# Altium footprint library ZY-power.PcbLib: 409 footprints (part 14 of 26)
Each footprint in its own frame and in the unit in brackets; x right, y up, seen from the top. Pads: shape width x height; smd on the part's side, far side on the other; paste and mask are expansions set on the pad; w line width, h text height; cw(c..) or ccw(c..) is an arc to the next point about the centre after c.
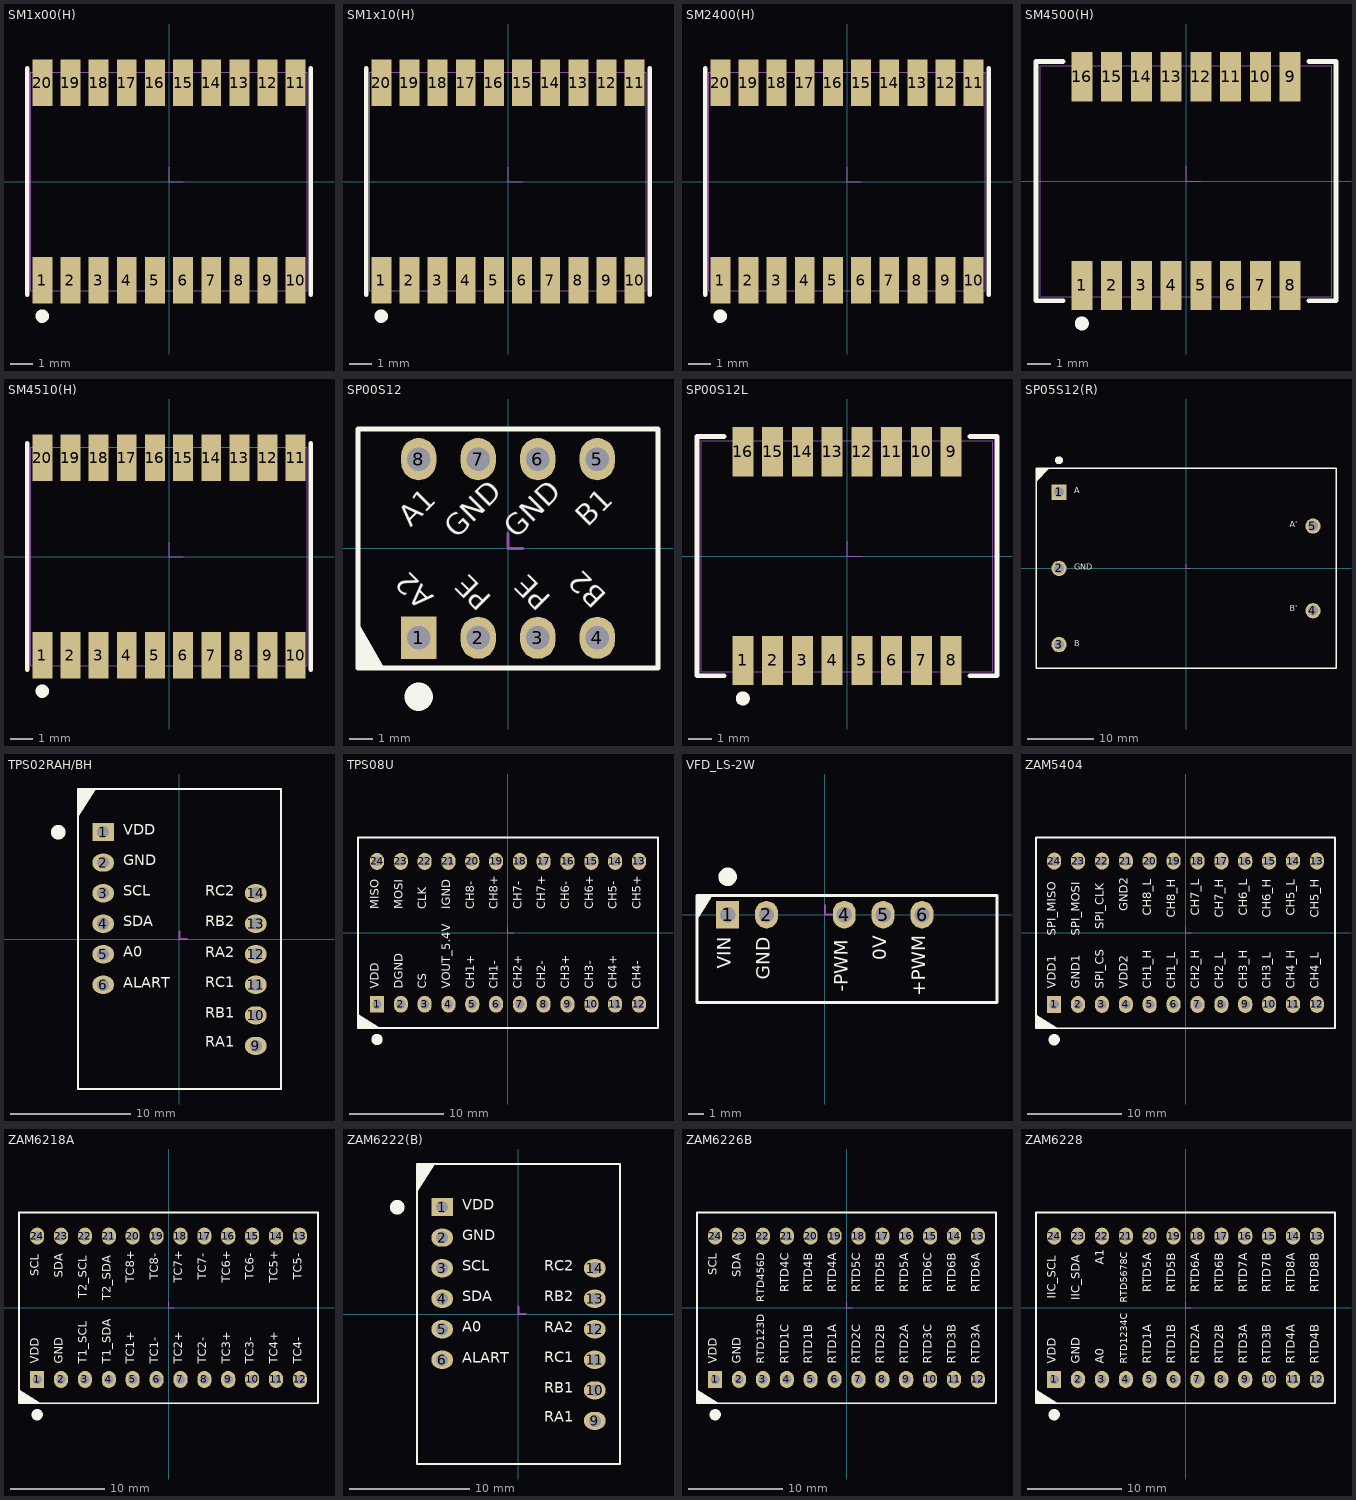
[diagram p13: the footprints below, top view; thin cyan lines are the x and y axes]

## SM1x00(H) [mm]
height 3
pads (20):
  rect 0.9x2.1 smd: 1(-5.715,-4.45) 2(-4.445,-4.45) 3(-3.175,-4.45) 4(-1.905,-4.45) 5(-0.635,-4.45) 6(0.635,-4.45) 7(1.905,-4.45) 8(3.175,-4.45) 9(4.445,-4.45) 10(5.715,-4.45) 11(5.715,4.45) 12(4.445,4.45) 13(3.175,4.45) 14(1.905,4.45) 15(0.635,4.45) 16(-0.635,4.45) 17(-1.905,4.45) 18(-3.175,4.45) 19(-4.445,4.45) 20(-5.715,4.45)
Top Overlay:
  circle w0.4: c-5.715,-6.074 r0.1
  lines w0.2: -6.4,-5.1 -6.4,5.1 ; 6.4,-5.1 6.4,5.1
Mechanical 13:
  lines w0.05: -6.225,-4.925 -6.225,4.925 6.225,4.925 6.225,-4.925 -6.225,-4.925
Mechanical 15:
  lines w0.05: 0,0.635 0,0 0.635,0

## SM1x10(H) [mm]
height 3
pads (20):
  rect 0.9x2.1 smd: 1(-5.715,-4.45) 2(-4.445,-4.45) 3(-3.175,-4.45) 4(-1.905,-4.45) 5(-0.635,-4.45) 6(0.635,-4.45) 7(1.905,-4.45) 8(3.175,-4.45) 9(4.445,-4.45) 10(5.715,-4.45) 11(5.715,4.45) 12(4.445,4.45) 13(3.175,4.45) 14(1.905,4.45) 15(0.635,4.45) 16(-0.635,4.45) 17(-1.905,4.45) 18(-3.175,4.45) 19(-4.445,4.45) 20(-5.715,4.45)
Top Overlay:
  circle w0.4: c-5.715,-6.074 r0.1
  lines w0.2: -6.4,-5.1 -6.4,5.1 ; 6.4,-5.1 6.4,5.1
Mechanical 13:
  lines w0.05: -6.225,-4.925 -6.225,4.925 6.225,4.925 6.225,-4.925 -6.225,-4.925
Mechanical 15:
  lines w0.05: 0,0.635 0,0 0.635,0

## SM2400(H) [mm]
height 3
pads (20):
  rect 0.9x2.1 smd: 1(-5.715,-4.45) 2(-4.445,-4.45) 3(-3.175,-4.45) 4(-1.905,-4.45) 5(-0.635,-4.45) 6(0.635,-4.45) 7(1.905,-4.45) 8(3.175,-4.45) 9(4.445,-4.45) 10(5.715,-4.45) 11(5.715,4.45) 12(4.445,4.45) 13(3.175,4.45) 14(1.905,4.45) 15(0.635,4.45) 16(-0.635,4.45) 17(-1.905,4.45) 18(-3.175,4.45) 19(-4.445,4.45) 20(-5.715,4.45)
Top Overlay:
  circle w0.4: c-5.715,-6.074 r0.1
  lines w0.2: -6.4,-5.1 -6.4,5.1 ; 6.4,-5.1 6.4,5.1
Mechanical 13:
  lines w0.05: -6.225,-4.925 6.225,-4.925 6.225,4.925 -6.225,4.925 -6.225,-4.925
Mechanical 15:
  lines w0.05: 0,0.635 0,0 0.635,0

## SM4500(H) [mm]
height 3
pads (16):
  rect 0.9x2.1 smd: 1(-4.445,-4.45) 2(-3.175,-4.45) 3(-1.905,-4.45) 4(-0.635,-4.45) 5(0.635,-4.45) 6(1.905,-4.45) 7(3.175,-4.45) 8(4.445,-4.45) 9(4.445,4.45) 10(3.175,4.45) 11(1.905,4.45) 12(0.635,4.45) 13(-0.635,4.45) 14(-1.905,4.45) 15(-3.175,4.45) 16(-4.445,4.45)
Top Overlay:
  circle w0.4: c-4.445,-6.074 r0.1
  lines w0.2: -5.232,-5.1 -6.4,-5.1 -6.4,5.1 -5.232,5.1 ; 5.232,-5.1 6.4,-5.1 6.4,5.1 5.232,5.1
Mechanical 13:
  lines w0.05: -6.225,-4.925 6.225,-4.925 6.225,4.925 -6.225,4.925 -6.225,-4.925
Mechanical 15:
  lines w0.05: 0,0.635 0,0 0.635,0
3D body "SM4500.stp": height 3.01, standoff -0.01, extent -6.225,-4.925 6.225,4.925

## SM4510(H) [mm]
height 3
pads (20):
  rect 0.9x2.1 smd: 1(-5.715,-4.45) 2(-4.445,-4.45) 3(-3.175,-4.45) 4(-1.905,-4.45) 5(-0.635,-4.45) 6(0.635,-4.45) 7(1.905,-4.45) 8(3.175,-4.45) 9(4.445,-4.45) 10(5.715,-4.45) 11(5.715,4.45) 12(4.445,4.45) 13(3.175,4.45) 14(1.905,4.45) 15(0.635,4.45) 16(-0.635,4.45) 17(-1.905,4.45) 18(-3.175,4.45) 19(-4.445,4.45) 20(-5.715,4.45)
Top Overlay:
  circle w0.4: c-5.715,-6.074 r0.1
  lines w0.2: -6.4,-5.1 -6.4,5.1 ; 6.4,-5.1 6.4,5.1
Mechanical 13:
  lines w0.05: -6.225,-4.925 -6.225,4.925 6.225,4.925 6.225,-4.925 -6.225,-4.925
Mechanical 15:
  lines w0.05: 0,0.635 0,0 0.635,0

## SP00S12 [mm]
height 7.7
pads (8):
  rect 1.5x1.8 hole 1: 1(-3.81,-3.81)
  oval 1.5x1.8 hole 1: 2(-1.27,-3.81) 3(1.27,-3.81) 4(3.81,-3.81) 5(3.81,3.81) 6(1.27,3.81) 7(-1.27,3.81) 8(-3.81,3.81)
Top Overlay:
  circle w1: c-3.81,-6.325 r0.1
  region: -5.284,-5.1 -6.4,-3.161 -6.4,-5.1
  lines w0.2: -6.4,-5.1 6.4,-5.1 6.4,5.1 -6.4,5.1 -6.4,-5.1
  text "A2" at -2.921,-1.849 h1.52
  text "PE" at -0.432,-1.88 h1.52
  text "PE" at 2.108,-1.88 h1.52
  text "B2" at 4.47,-1.778 h1.52
  text "A1" at -3.937,0.674 h1.52
  text "GND" at -1.981,0.178 h1.52
  text "GND" at 0.559,0.178 h1.52
  text "B1" at 3.607,0.674 h1.52
Mechanical 15:
  lines w0.127: 0,0.635 0,0 0.635,0
3D body: height 7.7, standoff 0, extent -6.4,-5.1 6.4,5.1
3D body "zhen01.stp": height 6.09, standoff -4.41, extent -4.06,-4.06 -3.56,-3.56
3D body "zhen01.stp": height 6.09, standoff -4.41, extent -1.52,-4.06 -1.02,-3.56
3D body "zhen01.stp": height 6.09, standoff -4.41, extent 1.02,-4.06 1.52,-3.56
3D body "zhen01.stp": height 6.09, standoff -4.41, extent 3.56,-4.06 4.06,-3.56
3D body "zhen01.stp": height 6.09, standoff -4.41, extent 3.56,3.56 4.06,4.06
3D body "zhen01.stp": height 6.09, standoff -4.41, extent 1.02,3.56 1.52,4.06
3D body "zhen01.stp": height 6.09, standoff -4.41, extent -1.52,3.56 -1.02,4.06
3D body "zhen01.stp": height 6.09, standoff -4.41, extent -4.06,3.56 -3.56,4.06

## SP00S12L [mm]
height 3
pads (16):
  rect 0.9x2.1 smd: 1(-4.445,-4.45) 2(-3.175,-4.45) 3(-1.905,-4.45) 4(-0.635,-4.45) 5(0.635,-4.45) 6(1.905,-4.45) 7(3.175,-4.45) 8(4.445,-4.45) 9(4.445,4.45) 10(3.175,4.45) 11(1.905,4.45) 12(0.635,4.45) 13(-0.635,4.45) 14(-1.905,4.45) 15(-3.175,4.45) 16(-4.445,4.45)
Top Overlay:
  circle w0.4: c-4.445,-6.074 r0.1
  lines w0.2: -5.232,-5.1 -6.4,-5.1 -6.4,5.1 -5.232,5.1 ; 5.232,-5.1 6.4,-5.1 6.4,5.1 5.232,5.1
Mechanical 13:
  lines w0.05: -6.225,-4.925 -6.225,4.925 6.225,4.925 6.225,-4.925 -6.225,-4.925
Mechanical 15:
  lines w0.05: 0,0.635 0,0 0.635,0
3D body "SP00S12.stp": height 3.01, standoff -0.01, extent -6.225,-4.925 6.225,4.925

## SP05S12(R) [mm]
height 21.2
pads (5):
  rect 2.3x2.3 hole 1.5: 1(-19.05,11.43)
  round 2.3 hole 1.5: 2(-19.05,0) 3(-19.05,-11.43) 4(19.05,-6.35) 5(19.05,6.35)
Top Overlay:
  circle w1: c-19.05,16.225 r0.1
  region: -22.5,15 -22.5,13.025 -20.525,15
  lines w0.2: -22.5,-15 22.5,-15 22.5,15 -22.5,15 -22.5,-15
  text "B'" at 15.551,-6.731 h1.52
  text "A'" at 15.551,5.842 h1.52
  text "GND" at -16.764,-0.495 h1.52
  text "A" at -16.764,10.947 h1.52
  text "B" at -16.764,-11.938 h1.52
Mechanical 15:
  lines w0.127: 0,0.635 0,0 0.635,0

## TPS02RAH/BH [mm]
height 8.1
pads (12):
  rect 1.8x1.5 hole 1: 1(-6.35,8.89)
  oval 1.8x1.5 hole 1: 2(-6.35,6.35) 3(-6.35,3.81) 4(-6.35,1.27) 5(-6.35,-1.27) 6(-6.35,-3.81) 9(6.35,-8.89) 10(6.35,-6.35) 11(6.35,-3.81) 12(6.35,-1.27) 13(6.35,1.27) 14(6.35,3.81)
Top Overlay:
  circle w1: c-10.098,8.89 r0.1
  region: -8.45,10.16 -8.45,12.49 -6.99,12.49
  lines w0.2: -8.45,-12.49 -8.45,12.49 8.45,12.49 8.45,-12.49 -8.45,-12.49
  text "A0" at -4.7,-1.778 h1.52
  text "ALART" at -4.7,-4.335 h1.52
  text "SDA" at -4.7,0.762 h1.52
  text "SCL" at -4.7,3.302 h1.52
  text "GND" at -4.7,5.842 h1.52
  text "VDD" at -4.699,8.382 h1.52
  text "RB1" at 2.162,-6.858 h1.52
  text "RA1" at 2.162,-9.271 h1.52
  text "RC1" at 2.162,-4.318 h1.52
  text "RA2" at 2.162,-1.795 h1.52
  text "RB2" at 2.162,0.762 h1.52
  text "RC2" at 2.162,3.302 h1.52
Mechanical 15:
  lines w0.127: 0,0.635 0,0 0.635,0
3D body "zhen01.stp": height 6.09, standoff -4.41, extent 6.1,-6.6 6.6,-6.1
3D body "zhen01.stp": height 6.09, standoff -4.41, extent 6.1,-4.06 6.6,-3.56
3D body "zhen01.stp": height 6.09, standoff -4.41, extent 6.1,-1.52 6.6,-1.02
3D body "zhen01.stp": height 6.09, standoff -4.41, extent 6.1,1.02 6.6,1.52
3D body "zhen01.stp": height 6.09, standoff -4.41, extent 6.1,3.56 6.6,4.06
3D body "zhen01.stp": height 6.09, standoff -4.41, extent 6.1,-9.14 6.6,-8.64
3D body "zhen01.stp": height 6.09, standoff -4.41, extent -6.6,-4.06 -6.1,-3.56
3D body "zhen01.stp": height 6.09, standoff -4.41, extent -6.6,8.64 -6.1,9.14
3D body "zhen01.stp": height 6.09, standoff -4.41, extent -6.6,6.1 -6.1,6.6
3D body "zhen01.stp": height 6.09, standoff -4.41, extent -6.6,3.56 -6.1,4.06
3D body "zhen01.stp": height 6.09, standoff -4.41, extent -6.6,1.02 -6.1,1.52
3D body "zhen01.stp": height 6.09, standoff -4.41, extent -6.6,-1.52 -6.1,-1.02
3D body: height 7.1, standoff 0, extent -8.45,-12.49 8.45,12.49

## TPS08U [mm]
height 10.2
pads (24):
  rect 1.5x1.8 hole 1: 1(-13.97,-7.62)
  oval 1.5x1.8 hole 1: 2(-11.43,-7.62) 3(-8.89,-7.62) 4(-6.35,-7.62) 5(-3.81,-7.62) 6(-1.27,-7.62) 7(1.27,-7.62) 8(3.81,-7.62) 9(6.35,-7.62) 10(8.89,-7.62) 11(11.43,-7.62) 12(13.97,-7.62) 13(13.97,7.62) 14(11.43,7.62) 15(8.89,7.62) 16(6.35,7.62) 17(3.81,7.62) 18(1.27,7.62) 19(-1.27,7.62) 20(-3.81,7.62) 21(-6.35,7.62) 22(-8.89,7.62) 23(-11.43,7.62) 24(-13.97,7.62)
Top Overlay:
  circle w1: c-13.97,-11.368 r0.1
  region: -13.773,-10.15 -16,-10.15 -16,-8.69 -13.849,-10.038
  lines w0.2: -16,-10.15 16,-10.15 16,10.15 -16,10.15 -16,-10.15
  text "IGND" at -5.842,2.541 h1.52
  text "CH8+" at -0.762,2.541 h1.52
  text "CH8-" at -3.302,2.541 h1.52
  text "CH7+" at 4.318,2.541 h1.52
  text "CH7-" at 1.778,2.541 h1.52
  text "CH6+" at 9.398,2.541 h1.52
  text "CH6-" at 6.858,2.541 h1.52
  text "CH4+" at 11.938,-5.97 h1.52
  text "CH4-" at 14.478,-5.97 h1.52
  text "CH3+" at 6.858,-5.97 h1.52
  text "CH3-" at 9.398,-5.97 h1.52
  text "CH2+" at 1.778,-5.97 h1.52
  text "CH2-" at 4.318,-5.97 h1.52
  text "CLK" at -8.382,2.541 h1.52
  text "MOSI" at -10.922,2.541 h1.52
  text "MISO" at -13.462,2.541 h1.52
  text "CH1-" at -0.762,-5.97 h1.52
  text "CH1+" at -3.302,-5.97 h1.52
  text "CS" at -8.382,-5.97 h1.52
  text "DGND" at -10.922,-5.97 h1.52
  text "VDD" at -13.462,-5.969 h1.52
  text "CH5-" at 11.938,2.541 h1.52
  text "CH5+" at 14.478,2.541 h1.52
  text "VOUT_5.4V" at -5.842,-5.969 h1.52
Mechanical 15:
  lines w0.127: 0,0.635 0,0 0.635,0
3D body: height 6.62, standoff 0, extent -14.732,-8.382 -13.208,-6.858
3D body: height 6.6, standoff 0, extent -16,-10.15 16,10.15
3D body "zhen01.stp": height 6.09, standoff -4.41, extent -14.22,7.37 -13.72,7.87
3D body "zhen01.stp": height 6.09, standoff -4.41, extent -11.68,7.37 -11.18,7.87
3D body "zhen01.stp": height 6.09, standoff -4.41, extent -9.14,7.37 -8.64,7.87
3D body "zhen01.stp": height 6.09, standoff -4.41, extent -6.6,7.37 -6.1,7.87
3D body "zhen01.stp": height 6.09, standoff -4.41, extent -4.06,7.37 -3.56,7.87
3D body "zhen01.stp": height 6.09, standoff -4.41, extent -1.52,7.37 -1.02,7.87
3D body "zhen01.stp": height 6.09, standoff -4.41, extent 1.02,7.37 1.52,7.87
3D body "zhen01.stp": height 6.09, standoff -4.41, extent 3.56,7.37 4.06,7.87
3D body "zhen01.stp": height 6.09, standoff -4.41, extent 6.1,7.37 6.6,7.87
3D body "zhen01.stp": height 6.09, standoff -4.41, extent 8.64,7.37 9.14,7.87
3D body "zhen01.stp": height 6.09, standoff -4.41, extent 11.18,7.37 11.68,7.87
3D body "zhen01.stp": height 6.09, standoff -4.41, extent 13.72,7.37 14.22,7.87
3D body "zhen01.stp": height 6.09, standoff -4.41, extent 13.72,-7.87 14.22,-7.37
3D body "zhen01.stp": height 6.09, standoff -4.41, extent 11.18,-7.87 11.68,-7.37
3D body "zhen01.stp": height 6.09, standoff -4.41, extent 8.64,-7.87 9.14,-7.37
3D body "zhen01.stp": height 6.09, standoff -4.41, extent 6.1,-7.87 6.6,-7.37
3D body "zhen01.stp": height 6.09, standoff -4.41, extent 3.56,-7.87 4.06,-7.37
3D body "zhen01.stp": height 6.09, standoff -4.41, extent 1.02,-7.87 1.52,-7.37
3D body "zhen01.stp": height 6.09, standoff -4.41, extent -1.52,-7.87 -1.02,-7.37
3D body "zhen01.stp": height 6.09, standoff -4.41, extent -4.06,-7.87 -3.56,-7.37
3D body "zhen01.stp": height 6.09, standoff -4.41, extent -6.6,-7.87 -6.1,-7.37
3D body "zhen01.stp": height 6.09, standoff -4.41, extent -9.14,-7.87 -8.64,-7.37
3D body "zhen01.stp": height 6.09, standoff -4.41, extent -11.68,-7.87 -11.18,-7.37
3D body "zhen01.stp": height 6.09, standoff -4.41, extent -14.22,-7.87 -13.72,-7.37

## VFD_LS-2W [mm]
pads (5):
  rect 1.5x1.8 hole 1: 1(-6.35,0)
  oval 1.5x1.8 hole 1: 2(-3.81,0) 4(1.27,0) 5(3.81,0) 6(6.35,0)
Top Overlay:
  circle w1: c-6.35,2.475 r0.1
  region: -8.35,-0.336 -8.35,1.25 -7.356,1.25
  lines w0.2: -8.35,-5.75 11.25,-5.75 11.25,1.25 -8.35,1.25 -8.35,-5.75
  text "VIN" at -5.842,-3.538 h1.52
  text "GND" at -3.302,-4.264 h1.52
  text "-PWM" at 1.778,-5.022 h1.52
  text "0V" at 4.318,-2.982 h1.52
  text "+PWM" at 6.858,-5.334 h1.52
Mechanical 15:
  lines w0.127: 0,0.635 0,0 0.635,0

## ZAM5404 [mm]
height 6.5
pads (24):
  rect 1.5x1.8 hole 1: 1(-13.97,-7.62)
  oval 1.5x1.8 hole 1: 2(-11.43,-7.62) 3(-8.89,-7.62) 4(-6.35,-7.62) 5(-3.81,-7.62) 6(-1.27,-7.62) 7(1.27,-7.62) 8(3.81,-7.62) 9(6.35,-7.62) 10(8.89,-7.62) 11(11.43,-7.62) 12(13.97,-7.62) 13(13.97,7.62) 14(11.43,7.62) 15(8.89,7.62) 16(6.35,7.62) 17(3.81,7.62) 18(1.27,7.62) 19(-1.27,7.62) 20(-3.81,7.62) 21(-6.35,7.62) 22(-8.89,7.62) 23(-11.43,7.62) 24(-13.97,7.62)
Top Overlay:
  circle w1: c-13.97,-11.368 r0.1
  region: -13.673,-10.15 -15.9,-10.15 -15.9,-8.69 -13.748,-10.038
  lines w0.2: -15.9,-10.15 15.9,-10.15 15.9,10.15 -15.9,10.15 -15.9,-10.15
  text "CH7_L" at 1.778,1.79 h1.52
  text "CH8_H" at -0.762,1.626 h1.52
  text "CH8_L" at -3.302,1.79 h1.52
  text "GND2" at -5.842,2.275 h1.52
  text "SPI_CLK" at -8.382,0.374 h1.52
  text "SPI_MOSI" at -10.922,-0.339 h1.52
  text "SPI_MISO" at -13.462,-0.339 h1.52
  text "CH2_H" at 1.778,-5.969 h1.52
  text "CH1_L" at -0.762,-5.969 h1.52
  text "CH1_H" at -3.302,-5.969 h1.52
  text "VDD2" at -5.842,-5.969 h1.52
  text "SPI_CS" at -8.382,-5.969 h1.52
  text "GND1" at -10.922,-5.969 h1.52
  text "VDD1" at -13.462,-5.969 h1.52
  text "CH2_L" at 4.318,-5.969 h1.52
  text "CH3_H" at 6.858,-5.969 h1.52
  text "CH3_L" at 9.398,-5.969 h1.52
  text "CH4_H" at 11.938,-5.969 h1.52
  text "CH4_L" at 14.478,-5.969 h1.52
  text "CH7_H" at 4.318,1.626 h1.52
  text "CH6_L" at 6.858,1.79 h1.52
  text "CH6_H" at 9.398,1.626 h1.52
  text "CH5_L" at 11.938,1.79 h1.52
  text "CH5_H" at 14.478,1.626 h1.52
Mechanical 15:
  lines w0.127: 0,0.635 0,0 0.635,0

## ZAM6218A [mm]
height 6.5
pads (24):
  rect 1.5x1.8 hole 1: 1(-13.97,-7.62)
  oval 1.5x1.8 hole 1: 2(-11.43,-7.62) 3(-8.89,-7.62) 4(-6.35,-7.62) 5(-3.81,-7.62) 6(-1.27,-7.62) 7(1.27,-7.62) 8(3.81,-7.62) 9(6.35,-7.62) 10(8.89,-7.62) 11(11.43,-7.62) 12(13.97,-7.62) 13(13.97,7.62) 14(11.43,7.62) 15(8.89,7.62) 16(6.35,7.62) 17(3.81,7.62) 18(1.27,7.62) 19(-1.27,7.62) 20(-3.81,7.62) 21(-6.35,7.62) 22(-8.89,7.62) 23(-11.43,7.62) 24(-13.97,7.62)
Top Overlay:
  circle w1: c-13.97,-11.368 r0.1
  region: -13.673,-10.15 -15.9,-10.15 -15.9,-8.69 -13.748,-10.038
  lines w0.2: -15.9,-10.15 15.9,-10.15 15.9,10.15 -15.9,10.15 -15.9,-10.15
  text "T2_SDA" at -5.842,0.796 h1.52
  text "TC8-" at -0.762,2.961 h1.52
  text "TC8+" at -3.302,2.657 h1.52
  text "TC7-" at 4.318,2.961 h1.52
  text "TC7+" at 1.778,2.657 h1.52
  text "TC6-" at 9.398,2.961 h1.52
  text "TC6+" at 6.858,2.657 h1.52
  text "TC4+" at 11.938,-5.969 h1.52
  text "TC4-" at 14.478,-5.969 h1.52
  text "TC3+" at 6.858,-5.969 h1.52
  text "TC3-" at 9.398,-5.969 h1.52
  text "TC2+" at 1.778,-5.969 h1.52
  text "TC2-" at 4.318,-5.969 h1.52
  text "T2_SCL" at -8.382,0.996 h1.52
  text "SDA" at -10.922,3.175 h1.52
  text "SCL" at -13.462,3.376 h1.52
  text "TC1-" at -0.762,-5.969 h1.52
  text "TC1+" at -3.302,-5.969 h1.52
  text "T1_SCL" at -8.382,-5.969 h1.52
  text "GND" at -10.922,-5.969 h1.52
  text "VDD" at -13.462,-5.969 h1.52
  text "TC5+" at 11.938,2.657 h1.52
  text "TC5-" at 14.478,2.961 h1.52
  text "T1_SDA" at -5.842,-5.969 h1.52
Mechanical 15:
  lines w0.127: 0,0.635 0,0 0.635,0
3D body: height 6.62, standoff 0, extent -14.732,-8.382 -13.208,-6.858
3D body: height 6.6, standoff 0, extent -15.9,-10.15 15.9,10.15
3D body "zhen01.stp": height 6.09, standoff -4.41, extent -14.22,7.37 -13.72,7.87
3D body "zhen01.stp": height 6.09, standoff -4.41, extent -11.68,7.37 -11.18,7.87
3D body "zhen01.stp": height 6.09, standoff -4.41, extent -9.14,7.37 -8.64,7.87
3D body "zhen01.stp": height 6.09, standoff -4.41, extent -6.6,7.37 -6.1,7.87
3D body "zhen01.stp": height 6.09, standoff -4.41, extent -4.06,7.37 -3.56,7.87
3D body "zhen01.stp": height 6.09, standoff -4.41, extent -1.52,7.37 -1.02,7.87
3D body "zhen01.stp": height 6.09, standoff -4.41, extent 1.02,7.37 1.52,7.87
3D body "zhen01.stp": height 6.09, standoff -4.41, extent 3.56,7.37 4.06,7.87
3D body "zhen01.stp": height 6.09, standoff -4.41, extent 6.1,7.37 6.6,7.87
3D body "zhen01.stp": height 6.09, standoff -4.41, extent 8.64,7.37 9.14,7.87
3D body "zhen01.stp": height 6.09, standoff -4.41, extent 11.18,7.37 11.68,7.87
3D body "zhen01.stp": height 6.09, standoff -4.41, extent 13.72,7.37 14.22,7.87
3D body "zhen01.stp": height 6.09, standoff -4.41, extent 13.72,-7.87 14.22,-7.37
3D body "zhen01.stp": height 6.09, standoff -4.41, extent 11.18,-7.87 11.68,-7.37
3D body "zhen01.stp": height 6.09, standoff -4.41, extent 8.64,-7.87 9.14,-7.37
3D body "zhen01.stp": height 6.09, standoff -4.41, extent 6.1,-7.87 6.6,-7.37
3D body "zhen01.stp": height 6.09, standoff -4.41, extent 3.56,-7.87 4.06,-7.37
3D body "zhen01.stp": height 6.09, standoff -4.41, extent 1.02,-7.87 1.52,-7.37
3D body "zhen01.stp": height 6.09, standoff -4.41, extent -1.52,-7.87 -1.02,-7.37
3D body "zhen01.stp": height 6.09, standoff -4.41, extent -4.06,-7.87 -3.56,-7.37
3D body "zhen01.stp": height 6.09, standoff -4.41, extent -6.6,-7.87 -6.1,-7.37
3D body "zhen01.stp": height 6.09, standoff -4.41, extent -9.14,-7.87 -8.64,-7.37
3D body "zhen01.stp": height 6.09, standoff -4.41, extent -11.68,-7.87 -11.18,-7.37
3D body "zhen01.stp": height 6.09, standoff -4.41, extent -14.22,-7.87 -13.72,-7.37

## ZAM6222(B) [mm]
height 8.1
pads (12):
  rect 1.8x1.5 hole 1: 1(-6.35,8.89)
  oval 1.8x1.5 hole 1: 2(-6.35,6.35) 3(-6.35,3.81) 4(-6.35,1.27) 5(-6.35,-1.27) 6(-6.35,-3.81) 9(6.35,-8.89) 10(6.35,-6.35) 11(6.35,-3.81) 12(6.35,-1.27) 13(6.35,1.27) 14(6.35,3.81)
Top Overlay:
  circle w1: c-10.098,8.89 r0.1
  region: -8.45,10.16 -8.45,12.49 -6.99,12.49
  lines w0.2: -8.45,-12.49 -8.45,12.49 8.45,12.49 8.45,-12.49 -8.45,-12.49
  text "A0" at -4.7,-1.778 h1.52
  text "ALART" at -4.7,-4.335 h1.52
  text "SDA" at -4.7,0.762 h1.52
  text "SCL" at -4.7,3.302 h1.52
  text "GND" at -4.7,5.842 h1.52
  text "VDD" at -4.699,8.382 h1.52
  text "RB1" at 2.162,-6.858 h1.52
  text "RA1" at 2.162,-9.271 h1.52
  text "RC1" at 2.162,-4.318 h1.52
  text "RA2" at 2.162,-1.795 h1.52
  text "RB2" at 2.162,0.762 h1.52
  text "RC2" at 2.162,3.302 h1.52
Mechanical 15:
  lines w0.127: 0,0.635 0,0 0.635,0

## ZAM6226B [mm]
height 6.5
pads (24):
  rect 1.5x1.8 hole 1: 1(-13.97,-7.62)
  oval 1.5x1.8 hole 1: 2(-11.43,-7.62) 3(-8.89,-7.62) 4(-6.35,-7.62) 5(-3.81,-7.62) 6(-1.27,-7.62) 7(1.27,-7.62) 8(3.81,-7.62) 9(6.35,-7.62) 10(8.89,-7.62) 11(11.43,-7.62) 12(13.97,-7.62) 13(13.97,7.62) 14(11.43,7.62) 15(8.89,7.62) 16(6.35,7.62) 17(3.81,7.62) 18(1.27,7.62) 19(-1.27,7.62) 20(-3.81,7.62) 21(-6.35,7.62) 22(-8.89,7.62) 23(-11.43,7.62) 24(-13.97,7.62)
Top Overlay:
  circle w1: c-13.97,-11.368 r0.1
  region: -13.673,-10.15 -15.9,-10.15 -15.9,-8.69 -13.748,-10.038
  lines w0.2: -15.9,-10.15 15.9,-10.15 15.9,10.15 -15.9,10.15 -15.9,-10.15
  text "RTD4B" at -3.302,1.628 h1.52
  text "RTD5C" at 1.778,1.628 h1.52
  text "RTD4A" at -0.762,1.628 h1.52
  text "RTD456D" at -8.47,0.616 h1.4
  text "SDA" at -10.922,3.268 h1.52
  text "SCL" at -13.462,3.469 h1.52
  text "RTD2C" at 1.778,-5.969 h1.52
  text "RTD1A" at -0.762,-5.969 h1.52
  text "RTD1B" at -3.302,-5.969 h1.52
  text "RTD123D" at -8.47,-5.969 h1.4
  text "GND" at -10.922,-5.969 h1.52
  text "VDD" at -13.462,-5.969 h1.52
  text "RTD2B" at 4.318,-5.969 h1.52
  text "RTD2A" at 6.858,-5.969 h1.52
  text "RTD3C" at 9.398,-5.969 h1.52
  text "RTD3B" at 11.938,-5.969 h1.52
  text "RTD3A" at 14.478,-5.969 h1.52
  text "RTD5B" at 4.318,1.628 h1.52
  text "RTD5A" at 6.858,1.628 h1.52
  text "RTD6C" at 9.398,1.628 h1.52
  text "RTD6B" at 11.938,1.628 h1.52
  text "RTD6A" at 14.478,1.628 h1.52
  text "RTD1C" at -5.842,-5.969 h1.52
  text "RTD4C" at -5.842,1.628 h1.52
Mechanical 15:
  lines w0.127: 0,0.635 0,0 0.635,0
3D body: height 6.6, standoff 0, extent -15.9,-10.15 15.9,10.15
3D body "zhen01.stp": height 6.09, standoff -4.41, extent -14.22,7.37 -13.72,7.87
3D body "zhen01.stp": height 6.09, standoff -4.41, extent -11.68,7.37 -11.18,7.87
3D body "zhen01.stp": height 6.09, standoff -4.41, extent -9.14,7.37 -8.64,7.87
3D body "zhen01.stp": height 6.09, standoff -4.41, extent -6.6,7.37 -6.1,7.87
3D body "zhen01.stp": height 6.09, standoff -4.41, extent -4.06,7.37 -3.56,7.87
3D body "zhen01.stp": height 6.09, standoff -4.41, extent -1.52,7.37 -1.02,7.87
3D body "zhen01.stp": height 6.09, standoff -4.41, extent 1.02,7.37 1.52,7.87
3D body "zhen01.stp": height 6.09, standoff -4.41, extent 3.56,7.37 4.06,7.87
3D body "zhen01.stp": height 6.09, standoff -4.41, extent 6.1,7.37 6.6,7.87
3D body "zhen01.stp": height 6.09, standoff -4.41, extent 8.64,7.37 9.14,7.87
3D body "zhen01.stp": height 6.09, standoff -4.41, extent 11.18,7.37 11.68,7.87
3D body "zhen01.stp": height 6.09, standoff -4.41, extent 13.72,7.37 14.22,7.87
3D body "zhen01.stp": height 6.09, standoff -4.41, extent 13.72,-7.87 14.22,-7.37
3D body "zhen01.stp": height 6.09, standoff -4.41, extent 11.18,-7.87 11.68,-7.37
3D body "zhen01.stp": height 6.09, standoff -4.41, extent 8.64,-7.87 9.14,-7.37
3D body "zhen01.stp": height 6.09, standoff -4.41, extent 6.1,-7.87 6.6,-7.37
3D body "zhen01.stp": height 6.09, standoff -4.41, extent 3.56,-7.87 4.06,-7.37
3D body "zhen01.stp": height 6.09, standoff -4.41, extent 1.02,-7.87 1.52,-7.37
3D body "zhen01.stp": height 6.09, standoff -4.41, extent -1.52,-7.87 -1.02,-7.37
3D body "zhen01.stp": height 6.09, standoff -4.41, extent -4.06,-7.87 -3.56,-7.37
3D body "zhen01.stp": height 6.09, standoff -4.41, extent -6.6,-7.87 -6.1,-7.37
3D body "zhen01.stp": height 6.09, standoff -4.41, extent -9.14,-7.87 -8.64,-7.37
3D body "zhen01.stp": height 6.09, standoff -4.41, extent -11.68,-7.87 -11.18,-7.37
3D body "zhen01.stp": height 6.09, standoff -4.41, extent -14.22,-7.87 -13.72,-7.37
3D body: height 6.62, standoff 0, extent -14.732,-8.382 -13.208,-6.858

## ZAM6228 [mm]
height 6.5
pads (24):
  rect 1.5x1.8 hole 1: 1(-13.97,-7.62)
  oval 1.5x1.8 hole 1: 2(-11.43,-7.62) 3(-8.89,-7.62) 4(-6.35,-7.62) 5(-3.81,-7.62) 6(-1.27,-7.62) 7(1.27,-7.62) 8(3.81,-7.62) 9(6.35,-7.62) 10(8.89,-7.62) 11(11.43,-7.62) 12(13.97,-7.62) 13(13.97,7.62) 14(11.43,7.62) 15(8.89,7.62) 16(6.35,7.62) 17(3.81,7.62) 18(1.27,7.62) 19(-1.27,7.62) 20(-3.81,7.62) 21(-6.35,7.62) 22(-8.89,7.62) 23(-11.43,7.62) 24(-13.97,7.62)
Top Overlay:
  circle w1: c-13.97,-11.368 r0.1
  region: -13.673,-10.15 -15.9,-10.15 -15.9,-8.69 -13.748,-10.038
  lines w0.2: -15.9,-10.15 -15.9,10.15 15.9,10.15 15.9,-10.15 -15.9,-10.15
  text "RTD8B" at 14.478,1.628 h1.52
  text "RTD8A" at 11.938,1.628 h1.52
  text "RTD7B" at 9.398,1.628 h1.52
  text "RTD7A" at 6.858,1.628 h1.52
  text "RTD6B" at 4.318,1.628 h1.52
  text "RTD4B" at 14.478,-5.969 h1.52
  text "RTD4A" at 11.938,-5.969 h1.52
  text "RTD3B" at 9.398,-5.969 h1.52
  text "RTD3A" at 6.858,-5.969 h1.52
  text "RTD2B" at 4.318,-5.969 h1.52
  text "VDD" at -13.462,-5.969 h1.52
  text "GND" at -10.922,-5.969 h1.52
  text "A0" at -8.382,-5.969 h1.52
  text "RTD1234C" at -5.93,-5.969 h1.27
  text "RTD1A" at -3.302,-5.969 h1.52
  text "RTD1B" at -0.762,-5.969 h1.52
  text "RTD2A" at 1.778,-5.969 h1.52
  text "IIC_SCL" at -13.462,0.94 h1.52
  text "IIC_SDA" at -10.922,0.813 h1.52
  text "A1" at -8.382,4.572 h1.52
  text "RTD5678C" at -5.93,0.55 h1.27
  text "RTD5B" at -0.762,1.628 h1.52
  text "RTD6A" at 1.778,1.628 h1.52
  text "RTD5A" at -3.302,1.628 h1.52
Mechanical 15:
  lines w0.127: 0,0.635 0,0 0.635,0
3D body: height 6.6, standoff 0, extent -15.9,-10.15 15.9,10.15
3D body "zhen01.stp": height 6.09, standoff -4.41, extent -14.22,7.37 -13.72,7.87
3D body "zhen01.stp": height 6.09, standoff -4.41, extent -11.68,7.37 -11.18,7.87
3D body "zhen01.stp": height 6.09, standoff -4.41, extent -9.14,7.37 -8.64,7.87
3D body "zhen01.stp": height 6.09, standoff -4.41, extent -6.6,7.37 -6.1,7.87
3D body "zhen01.stp": height 6.09, standoff -4.41, extent -4.06,7.37 -3.56,7.87
3D body "zhen01.stp": height 6.09, standoff -4.41, extent -1.52,7.37 -1.02,7.87
3D body "zhen01.stp": height 6.09, standoff -4.41, extent 1.02,7.37 1.52,7.87
3D body "zhen01.stp": height 6.09, standoff -4.41, extent 3.56,7.37 4.06,7.87
3D body "zhen01.stp": height 6.09, standoff -4.41, extent 6.1,7.37 6.6,7.87
3D body "zhen01.stp": height 6.09, standoff -4.41, extent 8.64,7.37 9.14,7.87
3D body "zhen01.stp": height 6.09, standoff -4.41, extent 11.18,7.37 11.68,7.87
3D body "zhen01.stp": height 6.09, standoff -4.41, extent 13.72,7.37 14.22,7.87
3D body "zhen01.stp": height 6.09, standoff -4.41, extent 13.72,-7.87 14.22,-7.37
3D body "zhen01.stp": height 6.09, standoff -4.41, extent 11.18,-7.87 11.68,-7.37
3D body "zhen01.stp": height 6.09, standoff -4.41, extent 8.64,-7.87 9.14,-7.37
3D body "zhen01.stp": height 6.09, standoff -4.41, extent 6.1,-7.87 6.6,-7.37
3D body "zhen01.stp": height 6.09, standoff -4.41, extent 3.56,-7.87 4.06,-7.37
3D body "zhen01.stp": height 6.09, standoff -4.41, extent 1.02,-7.87 1.52,-7.37
3D body "zhen01.stp": height 6.09, standoff -4.41, extent -1.52,-7.87 -1.02,-7.37
3D body "zhen01.stp": height 6.09, standoff -4.41, extent -4.06,-7.87 -3.56,-7.37
3D body "zhen01.stp": height 6.09, standoff -4.41, extent -6.6,-7.87 -6.1,-7.37
3D body "zhen01.stp": height 6.09, standoff -4.41, extent -9.14,-7.87 -8.64,-7.37
3D body "zhen01.stp": height 6.09, standoff -4.41, extent -11.68,-7.87 -11.18,-7.37
3D body "zhen01.stp": height 6.09, standoff -4.41, extent -14.22,-7.87 -13.72,-7.37
3D body: height 6.62, standoff 0, extent -14.732,-8.382 -13.208,-6.858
